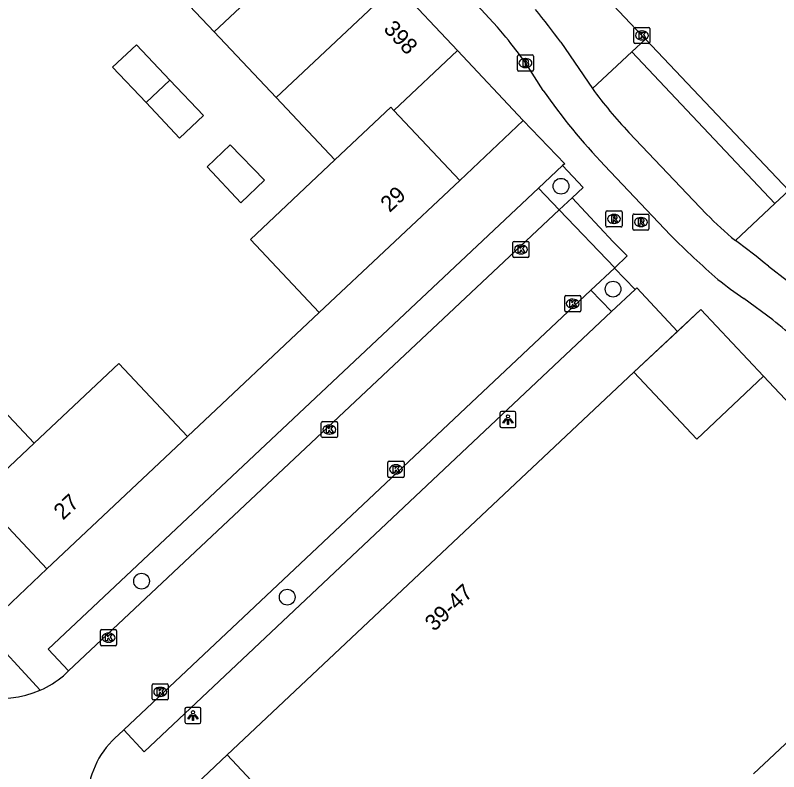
# Model space of a CAD drawing. Extents: x 162542 to 163144, y 380786 to 381511.
# Drawn here: x 163001.13 to 163048.52, y 381287.29 to 381334.24 of the extents above; entities that cross this region are included whole.
import ezdxf

# ---------------------------------------------------------------- set-up
doc = ezdxf.new("R2010")
doc.units = 0
for name, color, linetype in [('IMGEO_Boom', 7, 'Continuous'), ('IMGEO_Brandkraan', 7, 'Continuous'), ('IMGEO_Fietspad_gesloten', 7, 'Continuous'), ('IMGEO_Kolk', 7, 'Continuous'), ('IMGEO_Lichtpunt', 7, 'Continuous'), ('IMGEO_Muur', 7, 'Continuous'), ('IMGEO_Pand', 7, 'Continuous'), ('IMGEO_Pand_nummerreeks', 7, 'Continuous'), ('IMGEO_Parkeervlak_open', 7, 'Continuous'), ('IMGEO_Rijbaan_lokaal_gesloten', 7, 'Continuous'), ('IMGEO_Rijbaan_lokaal_open', 7, 'Continuous'), ('IMGEO_Rioolput', 7, 'Continuous'), ('IMGEO_Voetpad_open', 7, 'Continuous')]:
    doc.layers.add(name, color=color, linetype=linetype)

msp = doc.modelspace()

# ---------------------------------------------------------------- linework, layer by layer
at = {"layer": 'IMGEO_Boom'}
for centre in [(163035.009, 381323.628), (163038.238, 381317.241), (163008.971, 381299.115), (163018.015, 381298.124)]:
    msp.add_circle(centre, 0.489, dxfattribs=at)
at = {"layer": 'IMGEO_Brandkraan'}
for p, q in [((163032.299, 381330.846), (163032.299, 381331.698)), ((163032.374, 381331.772), (163033.226, 381331.772)), ((163032.787, 381331.552), (163032.812, 381331.552)), ((163033.3, 381331.698), (163033.3, 381330.846)), ((163033.226, 381330.772), (163032.374, 381330.772)), ((163032.81, 381330.992), (163032.785, 381330.992))]:
    msp.add_line(p, q, dxfattribs=at)
for points in [[(163032.299, 381330.846), (163032.299, 381331.698)], [(163032.374, 381331.772), (163033.226, 381331.772)], [(163033.3, 381331.698), (163033.3, 381330.846)], [(163032.647, 381331.472), (163032.647, 381331.072), (163032.86, 381331.072)], [(163032.878, 381331.472), (163032.647, 381331.472)], [(163032.826, 381331.391), (163032.772, 381331.391), (163032.772, 381331.315)], [(163032.772, 381331.315), (163032.825, 381331.315)], [(163032.834, 381331.239), (163032.772, 381331.239), (163032.772, 381331.158)], [(163032.772, 381331.158), (163032.834, 381331.158)], [(163033.226, 381330.772), (163032.374, 381330.772)]]:
    msp.add_lwpolyline(points, dxfattribs=at)
for centre, radius, start, end in [((163032.376, 381331.696), 0.0765, 91.552, 178.448), ((163032.376, 381331.696), 0.0765, 91.552, 178.448), ((163033.224, 381331.696), 0.0765, 1.552, 88.448), ((163033.224, 381331.696), 0.0765, 1.552, 88.448), ((163032.827, 381331.353), 0.0379, 267.8285, 90.9355), ((163032.835, 381331.198), 0.0404, 269.8759, 90.5077), ((163032.866, 381331.323), 0.251, 268.6676, 293.5347), ((163032.882, 381331.327), 0.145, 59.4692, 91.5367), ((163032.907, 381331.374), 0.0922, 285.5137, 58.1501), ((163032.912, 381331.182), 0.105, 301.3115, 78.989), ((163032.376, 381330.848), 0.0765, 181.552, 268.448), ((163032.376, 381330.848), 0.0765, 181.552, 268.448), ((163033.224, 381330.848), 0.0765, 271.552, 358.448), ((163033.224, 381330.848), 0.0765, 271.552, 358.448)]:
    msp.add_arc(centre, radius, start, end, dxfattribs=at)
for centre, major_axis, ratio, start_param, end_param in [((163032.786, 381331.272), (-0.387, 0.002), 0.722429, 4.712389, 7.853982), ((163032.811, 381331.272), (-0.39, 0.002), 0.717154, 1.570796, 4.712389)]:
    msp.add_ellipse(centre, major_axis=major_axis, ratio=ratio, start_param=start_param, end_param=end_param, dxfattribs=at)
at = {"layer": 'IMGEO_Fietspad_gesloten'}
for points in [[(163031.58, 381332.883), (163031.061, 381333.507), (163029.021, 381335.741), (162999.586, 381366.961), (162964.692, 381404.043), (162964.015, 381404.795)], [(163034.994, 381332.569), (163036.954, 381329.69)], [(163033.908, 381329.578), (163032.826, 381331.27)], [(163041.807, 381320.581), (163037.714, 381324.92)], [(163047.876, 381318.667), (163050.246, 381316.852), (163050.717, 381316.457)], [(163048.147, 381315.333), (163046.345, 381316.654)]]:
    msp.add_lwpolyline(points, dxfattribs=at)
for centre, radius, start, end in [((163001.253, 381307.949), 41.768, 36.1176, 39.6285), ((162999.141, 381306.537), 41.79, 36.2878, 39.0825), ((163062.927, 381349.405), 35.146, 214.3428, 224.1609), ((163084.464, 381363.352), 60.407, 225.07691, 228.8827), ((163024.453, 381290.651), 36.517, 50.1021, 54.1673), ((163072.823, 381354.043), 45.815, 232.1961, 234.695), ((163000.784, 381256.822), 75.278, 47.98349, 51.01081)]:
    msp.add_arc(centre, radius, start, end, dxfattribs=at)
at = {"layer": 'IMGEO_Kolk'}
for p, q in [((163039.529, 381332.562), (163039.529, 381333.414)), ((163039.604, 381333.488), (163040.456, 381333.488)), ((163040.53, 381333.414), (163040.53, 381332.562)), ((163040.017, 381333.268), (163040.042, 381333.268)), ((163040.456, 381332.488), (163039.604, 381332.488)), ((163040.04, 381332.708), (163040.015, 381332.708)), ((163032.019, 381319.28), (163032.019, 381320.132)), ((163032.094, 381320.206), (163032.946, 381320.206)), ((163033.02, 381320.132), (163033.02, 381319.28)), ((163032.507, 381319.986), (163032.532, 381319.986)), ((163032.946, 381319.206), (163032.094, 381319.206)), ((163032.53, 381319.426), (163032.505, 381319.426)), ((163035.309, 381316.837), (163036.161, 381316.837)), ((163035.234, 381315.911), (163035.234, 381316.763)), ((163035.722, 381316.617), (163035.747, 381316.617)), ((163036.235, 381316.763), (163036.235, 381315.911)), ((163035.745, 381316.057), (163035.72, 381316.057)), ((163036.161, 381315.837), (163035.309, 381315.837)), ((163020.13, 381308.097), (163020.13, 381308.949)), ((163020.205, 381309.023), (163021.057, 381309.023)), ((163020.618, 381308.803), (163020.643, 381308.803)), ((163021.131, 381308.949), (163021.131, 381308.097)), ((163021.057, 381308.023), (163020.205, 381308.023)), ((163020.641, 381308.243), (163020.616, 381308.243)), ((163024.263, 381305.63), (163024.263, 381306.482)), ((163024.338, 381306.556), (163025.19, 381306.556)), ((163025.264, 381306.482), (163025.264, 381305.63)), ((163024.751, 381306.336), (163024.776, 381306.336)), ((163025.19, 381305.556), (163024.338, 381305.556)), ((163024.774, 381305.776), (163024.749, 381305.776)), ((163006.422, 381295.183), (163006.422, 381296.035)), ((163006.497, 381296.109), (163007.349, 381296.109)), ((163007.423, 381296.035), (163007.423, 381295.183)), ((163006.91, 381295.889), (163006.935, 381295.889)), ((163007.349, 381295.109), (163006.497, 381295.109)), ((163006.933, 381295.329), (163006.908, 381295.329)), ((163009.629, 381291.818), (163009.629, 381292.67)), ((163009.704, 381292.744), (163010.556, 381292.744)), ((163010.63, 381292.67), (163010.63, 381291.818)), ((163010.117, 381292.524), (163010.142, 381292.524)), ((163010.556, 381291.744), (163009.704, 381291.744)), ((163010.14, 381291.964), (163010.115, 381291.964))]:
    msp.add_line(p, q, dxfattribs=at)
for points in [[(163039.529, 381332.562), (163039.529, 381333.414)], [(163039.604, 381333.488), (163040.456, 381333.488)], [(163040.53, 381333.414), (163040.53, 381332.562)], [(163039.85, 381333.188), (163039.973, 381333.188), (163039.973, 381333.037), (163040.103, 381333.188), (163040.267, 381333.188), (163040.121, 381333.037), (163040.274, 381332.788), (163040.122, 381332.788), (163040.037, 381332.952), (163039.973, 381332.885), (163039.973, 381332.788), (163039.85, 381332.788), (163039.85, 381333.188)], [(163040.456, 381332.488), (163039.604, 381332.488)], [(163032.019, 381319.28), (163032.019, 381320.132)], [(163032.094, 381320.206), (163032.946, 381320.206)], [(163033.02, 381320.132), (163033.02, 381319.28)], [(163032.34, 381319.906), (163032.463, 381319.906), (163032.463, 381319.755), (163032.593, 381319.906), (163032.757, 381319.906), (163032.611, 381319.755), (163032.764, 381319.506), (163032.612, 381319.506), (163032.527, 381319.67), (163032.463, 381319.603), (163032.463, 381319.506), (163032.34, 381319.506), (163032.34, 381319.906)], [(163032.946, 381319.206), (163032.094, 381319.206)], [(163035.309, 381316.837), (163036.161, 381316.837)], [(163035.234, 381315.911), (163035.234, 381316.763)], [(163035.555, 381316.537), (163035.678, 381316.537), (163035.678, 381316.386), (163035.808, 381316.537), (163035.972, 381316.537), (163035.826, 381316.386), (163035.979, 381316.137), (163035.827, 381316.137), (163035.742, 381316.301), (163035.678, 381316.234), (163035.678, 381316.137), (163035.555, 381316.137), (163035.555, 381316.537)], [(163036.235, 381316.763), (163036.235, 381315.911)], [(163036.161, 381315.837), (163035.309, 381315.837)], [(163020.13, 381308.097), (163020.13, 381308.949)], [(163020.205, 381309.023), (163021.057, 381309.023)], [(163021.131, 381308.949), (163021.131, 381308.097)], [(163020.451, 381308.723), (163020.574, 381308.723), (163020.574, 381308.572), (163020.704, 381308.723), (163020.868, 381308.723), (163020.722, 381308.572), (163020.875, 381308.323), (163020.723, 381308.323), (163020.638, 381308.487), (163020.574, 381308.42), (163020.574, 381308.323), (163020.451, 381308.323), (163020.451, 381308.723)], [(163021.057, 381308.023), (163020.205, 381308.023)], [(163024.263, 381305.63), (163024.263, 381306.482)], [(163024.338, 381306.556), (163025.19, 381306.556)], [(163025.264, 381306.482), (163025.264, 381305.63)], [(163024.584, 381306.256), (163024.707, 381306.256), (163024.707, 381306.105), (163024.837, 381306.256), (163025.001, 381306.256), (163024.855, 381306.105), (163025.008, 381305.856), (163024.856, 381305.856), (163024.771, 381306.02), (163024.707, 381305.953), (163024.707, 381305.856), (163024.584, 381305.856), (163024.584, 381306.256)], [(163025.19, 381305.556), (163024.338, 381305.556)], [(163006.422, 381295.183), (163006.422, 381296.035)], [(163006.497, 381296.109), (163007.349, 381296.109)], [(163007.423, 381296.035), (163007.423, 381295.183)], [(163006.743, 381295.809), (163006.866, 381295.809), (163006.866, 381295.658), (163006.996, 381295.809), (163007.16, 381295.809), (163007.014, 381295.658), (163007.167, 381295.409), (163007.015, 381295.409), (163006.93, 381295.573), (163006.866, 381295.506), (163006.866, 381295.409), (163006.743, 381295.409), (163006.743, 381295.809)], [(163007.349, 381295.109), (163006.497, 381295.109)], [(163009.629, 381291.818), (163009.629, 381292.67)], [(163009.704, 381292.744), (163010.556, 381292.744)], [(163010.63, 381292.67), (163010.63, 381291.818)], [(163009.95, 381292.444), (163010.073, 381292.444), (163010.073, 381292.293), (163010.203, 381292.444), (163010.367, 381292.444), (163010.221, 381292.293), (163010.374, 381292.044), (163010.222, 381292.044), (163010.137, 381292.208), (163010.073, 381292.141), (163010.073, 381292.044), (163009.95, 381292.044), (163009.95, 381292.444)], [(163010.556, 381291.744), (163009.704, 381291.744)]]:
    msp.add_lwpolyline(points, dxfattribs=at)
for centre, start, end in [((163039.606, 381333.412), 91.552, 178.448), ((163039.606, 381333.412), 91.552, 178.448), ((163040.454, 381333.412), 1.552, 88.448), ((163040.454, 381333.412), 1.552, 88.448), ((163039.606, 381332.564), 181.552, 268.448), ((163039.606, 381332.564), 181.552, 268.448), ((163040.454, 381332.564), 271.552, 358.448), ((163040.454, 381332.564), 271.552, 358.448), ((163032.096, 381320.13), 91.552, 178.448), ((163032.096, 381320.13), 91.552, 178.448), ((163032.944, 381320.13), 1.552, 88.448), ((163032.944, 381320.13), 1.552, 88.448), ((163032.096, 381319.282), 181.552, 268.448), ((163032.096, 381319.282), 181.552, 268.448), ((163032.944, 381319.282), 271.552, 358.448), ((163032.944, 381319.282), 271.552, 358.448), ((163035.311, 381316.761), 91.552, 178.448), ((163035.311, 381316.761), 91.552, 178.448), ((163036.159, 381316.761), 1.552, 88.448), ((163036.159, 381316.761), 1.552, 88.448), ((163035.311, 381315.913), 181.552, 268.448), ((163035.311, 381315.913), 181.552, 268.448), ((163036.159, 381315.913), 271.552, 358.448), ((163036.159, 381315.913), 271.552, 358.448), ((163020.207, 381308.947), 91.552, 178.448), ((163020.207, 381308.947), 91.552, 178.448), ((163021.055, 381308.947), 1.552, 88.448), ((163021.055, 381308.947), 1.552, 88.448), ((163020.207, 381308.099), 181.552, 268.448), ((163020.207, 381308.099), 181.552, 268.448), ((163021.055, 381308.099), 271.552, 358.448), ((163021.055, 381308.099), 271.552, 358.448), ((163024.34, 381306.48), 91.552, 178.448), ((163024.34, 381306.48), 91.552, 178.448), ((163025.188, 381306.48), 1.552, 88.448), ((163025.188, 381306.48), 1.552, 88.448), ((163024.34, 381305.632), 181.552, 268.448), ((163024.34, 381305.632), 181.552, 268.448), ((163025.188, 381305.632), 271.552, 358.448), ((163025.188, 381305.632), 271.552, 358.448), ((163006.499, 381296.033), 91.552, 178.448), ((163006.499, 381296.033), 91.552, 178.448), ((163007.347, 381296.033), 1.552, 88.448), ((163007.347, 381296.033), 1.552, 88.448), ((163006.499, 381295.185), 181.552, 268.448), ((163006.499, 381295.185), 181.552, 268.448), ((163007.347, 381295.185), 271.552, 358.448), ((163007.347, 381295.185), 271.552, 358.448), ((163009.706, 381292.668), 91.552, 178.448), ((163009.706, 381292.668), 91.552, 178.448), ((163010.554, 381292.668), 1.552, 88.448), ((163010.554, 381292.668), 1.552, 88.448), ((163009.706, 381291.82), 181.552, 268.448), ((163009.706, 381291.82), 181.552, 268.448), ((163010.554, 381291.82), 271.552, 358.448), ((163010.554, 381291.82), 271.552, 358.448)]:
    msp.add_arc(centre, 0.0765, start, end, dxfattribs=at)
for centre, major_axis, ratio, start_param, end_param in [((163040.016, 381332.988), (-0.387, 0.002), 0.722429, 4.712389, 7.853982), ((163040.041, 381332.988), (-0.39, 0.002), 0.717154, 1.570796, 4.712389), ((163032.506, 381319.706), (-0.387, 0.002), 0.722429, 4.712389, 7.853982), ((163032.531, 381319.706), (-0.39, 0.002), 0.717154, 1.570796, 4.712389), ((163035.721, 381316.337), (-0.387, 0.002), 0.722429, 4.712389, 7.853982), ((163035.746, 381316.337), (-0.39, 0.002), 0.717154, 1.570796, 4.712389), ((163020.617, 381308.523), (-0.387, 0.002), 0.722429, 4.712389, 7.853982), ((163020.642, 381308.523), (-0.39, 0.002), 0.717154, 1.570796, 4.712389), ((163024.75, 381306.056), (-0.387, 0.002), 0.722429, 4.712389, 7.853982), ((163024.775, 381306.056), (-0.39, 0.002), 0.717154, 1.570796, 4.712389), ((163006.909, 381295.609), (-0.387, 0.002), 0.722429, 4.712389, 7.853982), ((163006.934, 381295.609), (-0.39, 0.002), 0.717154, 1.570796, 4.712389), ((163010.116, 381292.244), (-0.387, 0.002), 0.722429, 4.712389, 7.853982), ((163010.141, 381292.244), (-0.39, 0.002), 0.717154, 1.570796, 4.712389)]:
    msp.add_ellipse(centre, major_axis=major_axis, ratio=ratio, start_param=start_param, end_param=end_param, dxfattribs=at)
at = {"layer": 'IMGEO_Lichtpunt'}
for p, q in [((163031.216, 381309.549), (163031.216, 381308.742)), ((163031.216, 381309.549), (163031.216, 381308.742)), ((163032.118, 381309.644), (163031.31, 381309.644)), ((163032.118, 381309.644), (163031.31, 381309.644)), ((163032.212, 381308.742), (163032.212, 381309.549)), ((163032.212, 381308.742), (163032.212, 381309.549)), ((163031.31, 381308.648), (163032.118, 381308.648)), ((163031.31, 381308.648), (163032.118, 381308.648)), ((163012.566, 381291.277), (163011.758, 381291.277)), ((163012.566, 381291.277), (163011.758, 381291.277)), ((163011.664, 381291.182), (163011.664, 381290.375)), ((163011.664, 381291.182), (163011.664, 381290.375)), ((163012.66, 381290.375), (163012.66, 381291.182)), ((163012.66, 381290.375), (163012.66, 381291.182)), ((163011.758, 381290.281), (163012.566, 381290.281)), ((163011.758, 381290.281), (163012.566, 381290.281))]:
    msp.add_line(p, q, dxfattribs=at)
for points in [[(163031.59, 381309.213), (163031.629, 381309.185), (163031.441, 381308.923), (163031.403, 381308.95), (163031.59, 381309.213)], [(163031.692, 381309.165), (163031.739, 381309.165), (163031.739, 381308.843), (163031.692, 381308.843), (163031.692, 381309.165)], [(163031.802, 381309.185), (163031.84, 381309.212), (163032.027, 381308.95), (163031.988, 381308.922), (163031.802, 381309.185)], [(163012.038, 381290.846), (163012.077, 381290.818), (163011.889, 381290.556), (163011.851, 381290.583), (163012.038, 381290.846)], [(163012.14, 381290.798), (163012.187, 381290.798), (163012.187, 381290.476), (163012.14, 381290.476), (163012.14, 381290.798)], [(163012.25, 381290.818), (163012.288, 381290.845), (163012.475, 381290.583), (163012.436, 381290.555), (163012.25, 381290.818)]]:
    msp.add_lwpolyline(points, dxfattribs=at)
for centre in [(163031.715, 381309.347), (163012.163, 381290.98)]:
    msp.add_circle(centre, 0.0994, dxfattribs=at)
for centre, start, end in [((163031.31, 381309.549), 90, 180), ((163031.31, 381309.549), 90, 180), ((163032.118, 381309.549), 0, 90), ((163032.118, 381309.549), 0, 90), ((163031.31, 381308.742), 180, 270), ((163031.31, 381308.742), 180, 270), ((163032.118, 381308.742), 270, 0), ((163032.118, 381308.742), 270, 360), ((163011.758, 381291.182), 90, 180), ((163011.758, 381291.182), 90, 180), ((163012.566, 381291.182), 0, 90), ((163012.566, 381291.182), 0, 90), ((163011.758, 381290.375), 180, 270), ((163011.758, 381290.375), 180, 270), ((163012.566, 381290.375), 270, 0), ((163012.566, 381290.375), 270, 360)]:
    msp.add_arc(centre, 0.0946, start, end, dxfattribs=at)
at = {"layer": 'IMGEO_Muur'}
for points in [[(163039.534, 381312.077), (163043.678, 381315.982)], [(163043.678, 381315.982), (163047.581, 381311.832)], [(163014.038, 381280.269), (163010.134, 381284.416), (163014.284, 381288.331)]]:
    msp.add_lwpolyline(points, dxfattribs=at)
at = {"layer": 'IMGEO_Pand'}
for points in [[(163020.924, 381340.201), (163013.478, 381333.2)], [(163013.478, 381333.2), (163010.004, 381336.883)], [(163024.758, 381336.124), (163017.318, 381329.129)], [(163024.758, 381336.124), (163028.591, 381332.047)], [(163017.318, 381329.129), (163013.478, 381333.2)], [(163009.252, 381328.817), (163007.172, 381331.015), (163008.656, 381332.407), (163010.73, 381330.215)], [(163028.591, 381332.047), (163024.636, 381328.326)], [(163010.73, 381330.215), (163012.814, 381328.012), (163011.331, 381326.618), (163009.252, 381328.817)], [(163010.73, 381330.215), (163009.252, 381328.817)], [(163020.969, 381325.257), (163017.318, 381329.129)], [(163024.636, 381328.326), (163024.442, 381328.532), (163020.969, 381325.257)], [(163024.636, 381328.326), (163028.718, 381323.992)], [(163014.478, 381326.19), (163016.605, 381323.993), (163015.129, 381322.593), (163013.039, 381324.821), (163014.478, 381326.19)], [(163020, 381315.783), (163015.727, 381320.313), (163020.969, 381325.257)], [(163028.718, 381323.992), (163020, 381315.783)], [(163002.302, 381307.676), (163007.562, 381312.631), (163011.833, 381308.097)], [(163014.284, 381288.331), (163039.534, 381312.077)], [(163039.534, 381312.077), (163043.431, 381307.931), (163047.581, 381311.832)], [(163047.581, 381311.832), (163059.616, 381299.052)], [(162998.819, 381311.374), (163002.302, 381307.676)], [(163011.833, 381308.097), (163003.102, 381299.878)], [(162999.182, 381304.046), (162998.837, 381304.412), (163002.302, 381307.676)], [(163003.102, 381299.878), (162999.182, 381304.046)], [(163050.865, 381290.828), (163046.955, 381287.149)], [(163014.284, 381288.331), (163018.168, 381284.171), (163014.038, 381280.269)]]:
    msp.add_lwpolyline(points, dxfattribs=at)
at = {"layer": 'IMGEO_Parkeervlak_open'}
for points in [[(163033.613, 381323.502), (163034.899, 381322.16)], [(163036.868, 381317.176), (163038.151, 381315.85)]]:
    msp.add_lwpolyline(points, dxfattribs=at)
at = {"layer": 'IMGEO_Rijbaan_lokaal_gesloten'}
for points in [[(163036.14, 381337.114), (163040.03, 381332.988), (163040.243, 381332.751)], [(163040.243, 381332.751), (163049.141, 381323.372)], [(163035.69, 381322.903), (163034.899, 381322.16)], [(163035.69, 381322.903), (163038.25, 381320.184), (163039.117, 381319.302), (163038.344, 381318.566)], [(163038.344, 381318.566), (163034.899, 381322.16)]]:
    msp.add_lwpolyline(points, dxfattribs=at)
at = {"layer": 'IMGEO_Rijbaan_lokaal_open'}
for points in [[(163039.397, 381331.964), (163040.243, 381332.751)], [(163036.954, 381329.69), (163039.397, 381331.964)], [(163039.397, 381331.964), (163048.274, 381322.556)], [(163039.218, 381326.96), (163044.046, 381321.894)], [(163048.274, 381322.556), (163049.141, 381323.372)], [(163045.831, 381320.257), (163048.274, 381322.556)], [(163034.899, 381322.16), (163004.431, 381293.548)], [(163036.868, 381317.176), (163038.325, 381318.547)], [(163038.325, 381318.547), (163038.344, 381318.566)], [(163007.88, 381289.893), (163036.868, 381317.176)], [(163004.431, 381293.548), (163004.123, 381293.243)], [(163007.545, 381289.569), (163007.88, 381289.893)]]:
    msp.add_lwpolyline(points, dxfattribs=at)
for centre, radius, start, end in [((163060.974, 381347.306), 29.788, 216.2561, 223.082), ((163060.954, 381338.539), 23.726, 224.5508, 230.4022), ((163000.247, 381297.898), 6.057, 222.7535, 293.7545), ((163000.253, 381297.889), 6.047, 293.7331, 309.7886), ((163010.964, 381285.459), 5.346, 129.7525, 222.7825)]:
    msp.add_arc(centre, radius, start, end, dxfattribs=at)
at = {"layer": 'IMGEO_Rioolput'}
for p, q in [((163037.796, 381321.171), (163037.796, 381322.023)), ((163037.871, 381322.097), (163038.723, 381322.097)), ((163038.797, 381322.023), (163038.797, 381321.171)), ((163038.284, 381321.877), (163038.309, 381321.877)), ((163039.467, 381320.977), (163039.467, 381321.829)), ((163039.542, 381321.903), (163040.394, 381321.903)), ((163039.955, 381321.683), (163039.98, 381321.683)), ((163040.468, 381321.829), (163040.468, 381320.977)), ((163038.723, 381321.097), (163037.871, 381321.097)), ((163038.307, 381321.317), (163038.282, 381321.317)), ((163039.978, 381321.123), (163039.953, 381321.123)), ((163040.394, 381320.903), (163039.542, 381320.903))]:
    msp.add_line(p, q, dxfattribs=at)
for points in [[(163037.796, 381321.171), (163037.796, 381322.023)], [(163037.871, 381322.097), (163038.723, 381322.097)], [(163038.797, 381322.023), (163038.797, 381321.171)], [(163038.385, 381321.795), (163038.133, 381321.797), (163038.133, 381321.397)], [(163038.133, 381321.397), (163038.257, 381321.397), (163038.257, 381321.559), (163038.268, 381321.559)], [(163038.311, 381321.716), (163038.257, 381321.716), (163038.257, 381321.635)], [(163038.257, 381321.635), (163038.309, 381321.635)], [(163039.467, 381320.977), (163039.467, 381321.829)], [(163039.542, 381321.903), (163040.394, 381321.903)], [(163040.056, 381321.601), (163039.804, 381321.603), (163039.804, 381321.203)], [(163040.468, 381321.829), (163040.468, 381320.977)], [(163038.723, 381321.097), (163037.871, 381321.097)], [(163038.315, 381321.53), (163038.386, 381321.397), (163038.526, 381321.397), (163038.461, 381321.523)], [(163039.804, 381321.203), (163039.928, 381321.203), (163039.928, 381321.365), (163039.939, 381321.365)], [(163039.982, 381321.522), (163039.928, 381321.522), (163039.928, 381321.441)], [(163039.928, 381321.441), (163039.98, 381321.441)], [(163039.986, 381321.336), (163040.057, 381321.203), (163040.197, 381321.203), (163040.132, 381321.329)], [(163040.394, 381320.903), (163039.542, 381320.903)]]:
    msp.add_lwpolyline(points, dxfattribs=at)
for centre, radius, start, end in [((163037.873, 381322.021), 0.0765, 91.552, 178.448), ((163037.873, 381322.021), 0.0765, 91.552, 178.448), ((163038.721, 381322.021), 0.0765, 1.552, 88.448), ((163038.721, 381322.021), 0.0765, 1.552, 88.448), ((163038.267, 381321.506), 0.0533, 26.0293, 88.6989), ((163038.293, 381321.824), 0.19, 274.7715, 282.9687), ((163038.317, 381321.62), 0.0964, 77.0061, 93.1865), ((163038.331, 381321.677), 0.0378, 276.6634, 79.6772), ((163038.384, 381321.685), 0.109, 350.3612, 89.416), ((163038.382, 381321.685), 0.112, 277.5842, 350.9817), ((163038.366, 381321.47), 0.108, 29.5134, 73.7905), ((163039.544, 381321.827), 0.0765, 91.552, 178.448), ((163039.544, 381321.827), 0.0765, 91.552, 178.448), ((163040.055, 381321.491), 0.109, 350.3612, 89.416), ((163040.392, 381321.827), 0.0765, 1.552, 88.448), ((163040.392, 381321.827), 0.0765, 1.552, 88.448), ((163037.873, 381321.173), 0.0765, 181.552, 268.448), ((163037.873, 381321.173), 0.0765, 181.552, 268.448), ((163038.721, 381321.173), 0.0765, 271.552, 358.448), ((163038.721, 381321.173), 0.0765, 271.552, 358.448), ((163039.938, 381321.312), 0.0533, 26.0293, 88.6989), ((163039.964, 381321.63), 0.19, 274.7715, 282.9687), ((163039.988, 381321.426), 0.0964, 77.0061, 93.1865), ((163040.002, 381321.483), 0.0378, 276.6634, 79.6772), ((163040.053, 381321.491), 0.112, 277.5842, 350.9817), ((163040.037, 381321.276), 0.108, 29.5134, 73.7905), ((163039.544, 381320.979), 0.0765, 181.552, 268.448), ((163039.544, 381320.979), 0.0765, 181.552, 268.448), ((163040.392, 381320.979), 0.0765, 271.552, 358.448), ((163040.392, 381320.979), 0.0765, 271.552, 358.448)]:
    msp.add_arc(centre, radius, start, end, dxfattribs=at)
for centre, major_axis, ratio, start_param, end_param in [((163038.283, 381321.597), (-0.387, 0.002), 0.722429, 4.712389, 7.853982), ((163038.308, 381321.597), (-0.39, 0.002), 0.717154, 1.570796, 4.712389), ((163039.954, 381321.403), (-0.387, 0.002), 0.722429, 4.712389, 7.853982), ((163039.979, 381321.403), (-0.39, 0.002), 0.717154, 1.570796, 4.712389)]:
    msp.add_ellipse(centre, major_axis=major_axis, ratio=ratio, start_param=start_param, end_param=end_param, dxfattribs=at)
at = {"layer": 'IMGEO_Voetpad_open'}
for points in [[(163028.591, 381332.047), (163032.668, 381327.711)], [(163032.668, 381327.711), (163028.718, 381323.992)], [(163032.668, 381327.711), (163035.234, 381325.026), (163035.104, 381324.904)], [(163033.613, 381323.502), (163035.104, 381324.904)], [(163035.104, 381324.904), (163036.378, 381323.549), (163035.69, 381322.903)], [(163004.431, 381293.548), (163003.18, 381294.889), (163033.613, 381323.502)], [(163038.325, 381318.547), (163039.607, 381317.221)], [(163039.607, 381317.221), (163039.714, 381317.322), (163042.231, 381314.618)], [(163039.607, 381317.221), (163038.151, 381315.85)], [(163042.231, 381314.618), (163043.678, 381315.982), (163047.581, 381311.832)], [(163038.151, 381315.85), (163009.125, 381288.527), (163007.88, 381289.893)], [(163011.833, 381308.097), (163020, 381315.783)], [(163039.534, 381312.077), (163042.231, 381314.618)], [(163003.102, 381299.878), (162999.157, 381296.164)], [(163002.687, 381292.354), (162999.157, 381296.164)], [(163010.134, 381284.416), (163014.284, 381288.331)]]:
    msp.add_lwpolyline(points, dxfattribs=at)

# ---------------------------------------------------------------- texts
at = {"layer": 'IMGEO_Pand_nummerreeks'}
for s, rotation, p in [('398', 313.2352, (163023.94, 381333.343)), ('29', 43.2755, (163024.374, 381321.962)), ('27', 43.2698, (163004.092, 381302.87)), ('39-47', 43.2698, (163027.132, 381295.955))]:
    msp.add_text(s, height=1, rotation=rotation, dxfattribs=at).set_placement(p)

doc.saveas('drawing.dxf')
